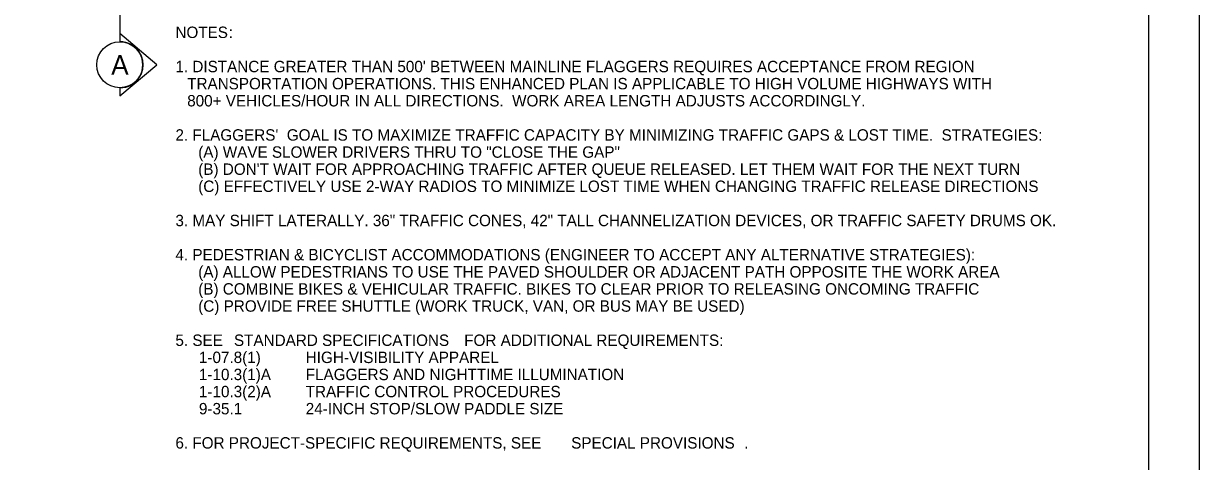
# Model space of a CAD drawing. Extents: x 99999.1 to 100095.7, y 99995 to 100010.7.
# Drawn here: x 100048.84 to 100056.06, y 100002.95 to 100005.63 of the extents above; entities that cross this region are included whole.
import ezdxf

# ---------------------------------------------------------------- set-up
doc = ezdxf.new("R2010")
doc.units = 0
for name, color, linetype in [('SH_GI_GeneralNotesBodyText', 7, 'Continuous'), ('SH_GI_PlotLimits', 7, 'Continuous'), ('SH_GI_SheetBorder', 7, 'Continuous'), ('SH_TI_WZSectionCut', 7, 'Continuous')]:
    doc.layers.add(name, color=color, linetype=linetype)

msp = doc.modelspace()

# ---------------------------------------------------------------- linework, layer by layer
at = {"layer": 'SH_GI_PlotLimits'}
msp.add_lwpolyline([(100039.0625, 99999.6875), (100056.0625, 99999.6875), (100056.0625, 100010.6875), (100039.0625, 100010.6875)], close=True, dxfattribs=at)
at = {"layer": 'SH_GI_SheetBorder'}
msp.add_line((100055.75, 100010.375), (100055.75, 100000), dxfattribs=at)
at = {"layer": 'SH_TI_WZSectionCut'}
for p, q in [((100049.4338, 100007.7022), (100049.4338, 100005.5723)), ((100049.4337, 100005.5723), (100049.4337, 100005.5224)), ((100049.6619, 100005.3812), (100049.4337, 100005.5723)), ((100049.4337, 100005.1901), (100049.6619, 100005.3812)), ((100049.4337, 100005.24), (100049.4337, 100005.1901))]:
    msp.add_line(p, q, dxfattribs=at)
msp.add_circle((100049.4338, 100005.3812), 0.1412, dxfattribs=at)
msp.add_arc((100049.4338, 100005.3812), 0.1412, 269.99779, 90.00221, dxfattribs=at)

# ---------------------------------------------------------------- texts
at = {"layer": 'SH_GI_GeneralNotesBodyText'}
for s, p in [('NOTES', (100049.7751, 100005.5456)), (':', (100050.1026, 100005.5456)), ("1. DISTANCE GREATER THAN 500' BETWEEN MAINLINE FLAGGERS REQUIRES ACCEPTANCE FROM REGION ", (100049.7751, 100005.3356)), ('TRANSPORTATION OPERATIONS. THIS ENHANCED PLAN IS APPLICABLE TO HIGH VOLUME HIGHWAYS WITH     ', (100049.8473, 100005.2306)), ('800+ VEHICLES/HOUR IN ALL DIRECTIONS.  WORK AREA LENGTH ADJUSTS ACCORDINGLY.', (100049.8473, 100005.1256)), ("2. FLAGGERS'  GOAL IS TO MAXIMIZE TRAFFIC CAPACITY BY MINIMIZING TRAFFIC GAPS & LOST TIME.  STRATEGIES:", (100049.7751, 100004.9156)), ('(A) WAVE SLOWER DRIVERS THRU TO "CLOSE THE GAP"', (100049.9151, 100004.8106)), ("(B) DON'T WAIT FOR APPROACHING TRAFFIC AFTER QUEUE RELEASED. LET THEM WAIT FOR THE NEXT TURN", (100049.9151, 100004.7056)), ('(C) EFFECTIVELY USE 2-WAY RADIOS TO MINIMIZE LOST TIME WHEN CHANGING TRAFFIC RELEASE DIRECTIONS', (100049.9151, 100004.6006)), ('3. MAY SHIFT LATERALLY. 36" TRAFFIC CONES, 42" TALL CHANNELIZATION DEVICES, OR TRAFFIC SAFETY DRUMS OK.', (100049.7751, 100004.3906)), ('4. PEDESTRIAN & BICYCLIST ACCOMMODATIONS (ENGINEER TO ACCEPT ANY ALTERNATIVE STRATEGIES):', (100049.7751, 100004.1806)), ('(A) ALLOW PEDESTRIANS TO USE THE PAVED SHOULDER OR ADJACENT PATH OPPOSITE THE WORK AREA', (100049.9151, 100004.0756)), ('(B) COMBINE BIKES & VEHICULAR TRAFFIC. BIKES TO CLEAR PRIOR TO RELEASING ONCOMING TRAFFIC', (100049.9151, 100003.9706)), ('(C) PROVIDE FREE SHUTTLE (WORK TRUCK, VAN, OR BUS MAY BE USED)', (100049.9151, 100003.8656)), ('5. SEE ', (100049.7751, 100003.6556)), ('STANDARD SPECIFICATIONS', (100050.1345, 100003.6556)), (' FOR ADDITIONAL REQUIREMENTS:', (100051.5222, 100003.6556)), ('1-07.8(1)', (100049.9195, 100003.5506)), ('HIGH-VISIBILITY APPAREL', (100050.5751, 100003.5506)), ('1-10.3(1)A', (100049.9195, 100003.4456)), ('FLAGGERS AND NIGHTTIME ILLUMINATION', (100050.5751, 100003.4456)), ('1-10.3(2)A', (100049.9195, 100003.3406)), ('TRAFFIC CONTROL PROCEDURES', (100050.5751, 100003.3406)), ('9-35.1', (100049.9195, 100003.2356)), ('24-INCH STOP/SLOW PADDLE SIZE', (100050.5751, 100003.2356)), ('6. FOR PROJECT-SPECIFIC REQUIREMENTS, SEE ', (100049.7751, 100003.0256)), ('SPECIAL PROVISIONS', (100052.2049, 100003.0256)), ('.', (100053.2667, 100003.0256))]:
    msp.add_text(s, height=0.07, rotation=360, dxfattribs=at).set_placement(p)
at = {"layer": 'SH_TI_WZSectionCut'}
msp.add_text('A', height=0.12, rotation=0.00995, dxfattribs=at).set_placement((100049.3808, 100005.3203))

doc.saveas('drawing.dxf')
